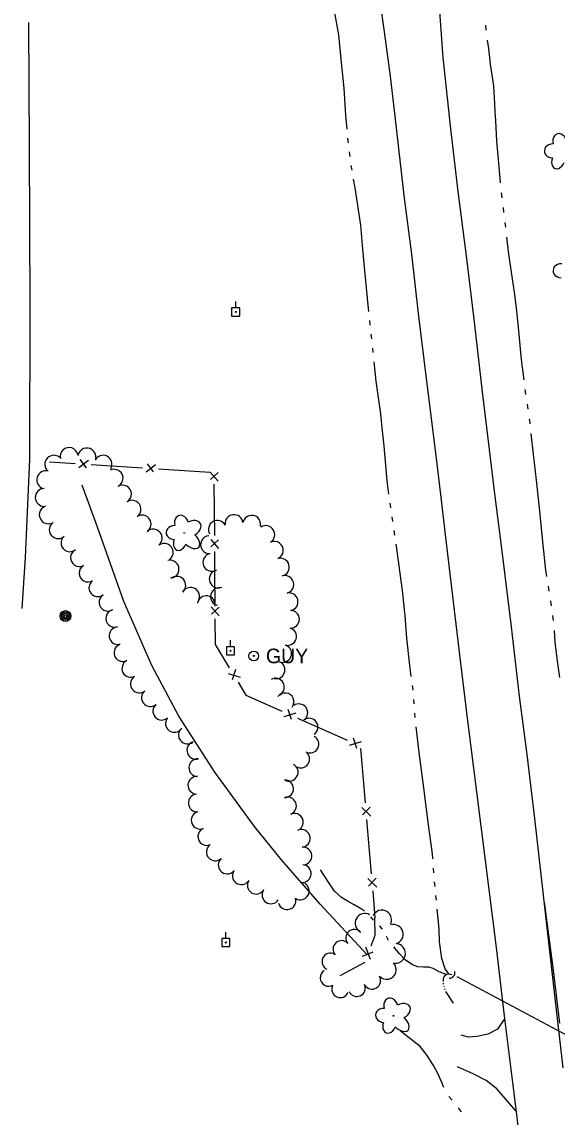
# Model space of a CAD drawing. Extents: x 589250 to 1188077, y 162953 to 363065.
# Drawn here: x 594851.6 to 595071.9, y 175168.1 to 175619.1 of the extents above; entities that cross this region are included whole.
import ezdxf

# ---------------------------------------------------------------- set-up
doc = ezdxf.new("R2010")
doc.units = 0
for name, color, linetype in [('E_DRN', 7, 'Continuous'), ('E_DRN_Pipe', 7, 'Continuous'), ('E_DWY', 7, 'Continuous'), ('E_FEN_P', 7, 'Continuous'), ('E_LAND_TreeLine_P', 7, 'Continuous'), ('E_LAND_Vegetation', 7, 'Continuous'), ('E_MISCPROP', 7, 'Continuous'), ('E_RDWY', 7, 'Continuous'), ('E_RDWY_Gravel', 7, 'Continuous'), ('E_RR_Abandoned', 7, 'Continuous'), ('E_UTL_EGuyWire', 7, 'Continuous'), ('E_UTL_EPowerPole', 7, 'Continuous'), ('E_WTR_FlowLine', 7, 'Continuous')]:
    doc.layers.add(name, color=color, linetype=linetype)

msp = doc.modelspace()

# ---------------------------------------------------------------- linework, layer by layer
at = {"layer": 'E_DRN'}
msp.add_arc((595027.62, 175227.53), 2.22, 266.2846, 12.5448, dxfattribs=at)
at = {"layer": 'E_DRN_Pipe'}
msp.add_line((595030.57, 175226.03), (595097.49, 175190.31), dxfattribs=at)
at = {"layer": 'E_DWY'}
for p, q in [((594854.29, 175618.91), (594854.66, 175567.59)), ((594854.66, 175567.59), (594854.86, 175502.45)), ((594854.86, 175502.45), (594854.81, 175439.04)), ((594854.81, 175439.04), (594852.91, 175398.48)), ((594852.91, 175398.48), (594851.63, 175377.48)), ((595050.22, 175208.51), (595047.37, 175204.33)), ((595047.37, 175204.33), (595043.36, 175202.25)), ((595035.42, 175201.05), (595032.45, 175201.82)), ((595038.93, 175201.24), (595035.42, 175201.05)), ((595043.36, 175202.25), (595038.93, 175201.24)), ((595037.67, 175185.72), (595030.89, 175188.85)), ((595042.69, 175183.23), (595037.67, 175185.72)), ((595047.06, 175179.79), (595042.69, 175183.23)), ((595055.01, 175170.56), (595047.06, 175179.79))]:
    msp.add_line(p, q, dxfattribs=at)
at = {"layer": 'E_FEN_P'}
for p, q in [((594863, 175437.91), (594873.57, 175437.24)), ((594875.1, 175435.65), (594878.99, 175438.62)), ((594875.47, 175438.85), (594878.04, 175435.53)), ((594880.11, 175436.82), (594890.68, 175436.14)), ((594890.68, 175436.14), (594901.24, 175435.46)), ((594902.77, 175433.88), (594906.66, 175436.85)), ((594903.15, 175437.07), (594905.71, 175433.75)), ((594907.78, 175435.04), (594918.35, 175434.36)), ((594918.35, 175434.36), (594928.91, 175433.69)), ((594929.14, 175433.65), (594932.38, 175429.99)), ((594932.36, 175433.51), (594929.23, 175430.71)), ((594930.66, 175428.74), (594930.74, 175418.15)), ((594930.74, 175418.15), (594930.82, 175407.56)), ((594929.35, 175405.92), (594932.59, 175402.26)), ((594932.56, 175405.78), (594929.44, 175402.98)), ((594930.87, 175401.01), (594930.95, 175390.42)), ((594930.95, 175390.42), (594931.03, 175379.83)), ((594929.55, 175378.19), (594932.79, 175374.53)), ((594932.77, 175378.05), (594929.64, 175375.25)), ((594931.07, 175373.28), (594931.15, 175362.69)), ((594931.15, 175362.69), (594936.97, 175353.09)), ((594939.53, 175352.41), (594938.2, 175348.16)), ((594936.52, 175350.8), (594941.46, 175349.22)), ((594940.58, 175347.15), (594943.8, 175341.83)), ((594943.8, 175341.83), (594948.38, 175339.8)), ((594948.38, 175339.8), (594958.65, 175335.25)), ((594959.59, 175333.11), (594964.55, 175334.64)), ((594961.13, 175336.15), (594962.47, 175331.91)), ((594965, 175332.43), (594975.27, 175327.89)), ((594975.27, 175327.89), (594985.54, 175323.34)), ((594986.48, 175321.2), (594991.44, 175322.73)), ((594988.02, 175324.24), (594989.36, 175320)), ((594991.01, 175319.9), (594991.96, 175308.71)), ((594991.96, 175308.71), (594992.91, 175297.52)), ((594991.49, 175295.66), (594995.21, 175292.05)), ((594994.9, 175295.77), (594991.82, 175292.56)), ((594993.5, 175290.59), (594994.45, 175279.4)), ((594994.45, 175279.4), (594995.39, 175268.21)), ((594993.97, 175266.36), (594997.7, 175262.75)), ((594997.38, 175266.47), (594994.31, 175263.25)), ((594995.98, 175261.29), (594996.93, 175250.1)), ((594997.02, 175243.01), (594996.93, 175250.1)), ((594995.41, 175238.69), (594997.02, 175243.01)), ((594991.79, 175234.42), (594996.12, 175236.09)), ((594995.06, 175233.01), (594993.15, 175238.07)), ((594982.57, 175226.36), (594992.87, 175231.91))]:
    msp.add_line(p, q, dxfattribs=at)
at = {"layer": 'E_LAND_TreeLine_P'}
for centre, radius, start, end in [((594871.06, 175440.13), 3.69, 13.4909, 193.4909), ((594878.33, 175439.96), 3.69, 352.1858, 172.1858), ((594864.73, 175436.96), 3.69, 47.686, 227.686), ((594885.01, 175436.94), 3.69, 332.6967, 152.6967), ((594861.45, 175430.55), 3.69, 73.4843, 253.4843), ((594889.56, 175431.18), 3.69, 296.8918, 116.8918), ((594860.83, 175423.26), 3.69, 90.8383, 270.8383), ((594892.99, 175424.64), 3.69, 301.6011, 121.6011), ((594862.46, 175416.13), 3.69, 107.9411, 287.9411), ((594896.94, 175418.41), 3.69, 304.5284, 124.5284), ((594901.1, 175412.31), 3.69, 303.5736, 123.5736), ((594938.91, 175412.48), 3.69, 7.2972, 187.2972), ((594946.19, 175412.21), 3.69, 347.9633, 167.9633), ((594866.58, 175410.02), 3.69, 124.7129, 304.7129), ((594932.07, 175410.09), 3.69, 29.4488, 209.4488), ((594951.97, 175407.97), 3.69, 302.2679, 122.2679), ((594871.37, 175404.54), 3.64, 130.361, 310.361), ((594905.64, 175406.5), 3.69, 310.1278, 130.1278), ((594928.84, 175403.82), 3.69, 94.1402, 274.1402), ((594875.27, 175398.46), 3.64, 116.1845, 296.1845), ((594910.16, 175400.66), 3.69, 306.376, 126.376), ((594955.51, 175401.51), 3.69, 293.8896, 113.8896), ((594912.59, 175393.75), 3.69, 284.5453, 104.5453), ((594929.8, 175396.56), 3.69, 112.8295, 292.8295), ((594957.97, 175394.57), 3.69, 284.8746, 104.8746), ((594878.83, 175392.11), 3.64, 121.0948, 301.0948), ((594932.41, 175389.68), 3.69, 99.9286, 279.9286), ((594882.86, 175386.07), 3.64, 127.4454, 307.4454), ((594915.35, 175387.09), 3.69, 312.147, 132.147), ((594959.83, 175387.43), 3.69, 284.4572, 104.4572), ((594921.03, 175382.54), 3.69, 330.9068, 150.9068), ((594932.95, 175382.43), 3.69, 75.7699, 255.7699), ((594961.61, 175380.32), 3.64, 283.6426, 103.6426), ((594887.03, 175380.11), 3.64, 123.3095, 303.3095), ((594927.48, 175379.09), 3.69, 350.054, 170.054), ((594889.83, 175373.46), 3.64, 107.0985, 287.0985), ((594962.17, 175373.11), 3.64, 269.8673, 89.8673), ((594891.19, 175366.33), 3.64, 98.3622, 278.3622), ((594961, 175366), 3.64, 253.6859, 73.6859), ((594893.19, 175359.36), 3.64, 108.8726, 288.8726), ((594958.95, 175359.01), 3.64, 248.1445, 68.1445), ((594896.44, 175352.85), 3.64, 117.4034, 297.4034), ((594956.24, 175352.26), 3.64, 248.1445, 68.1445), ((594899.92, 175346.48), 3.64, 129.2249, 309.2249), ((594955.99, 175345.18), 3.64, 299.7893, 119.7893), ((594904.53, 175340.84), 3.64, 129.2249, 309.2249), ((594959.92, 175339.13), 3.64, 322.9634, 142.9634), ((594965.59, 175334.62), 3.64, 305.5335, 125.5335), ((594909.18, 175335.25), 3.64, 131.0747, 311.0747), ((594914.35, 175330.19), 3.64, 144.4075, 324.4075), ((594969.82, 175328.7), 3.64, 305.5335, 125.5335), ((594919.74, 175325.4), 3.64, 128.4069, 308.4069), ((594970.22, 175321.67), 3.64, 242.1324, 62.1324), ((594923.19, 175319.12), 3.64, 107.7659, 287.7659), ((594966.39, 175315.55), 3.64, 225.0943, 45.0943), ((594924.01, 175311.99), 3.64, 88.3488, 268.3488), ((594961.64, 175310.1), 3.64, 241.2605, 61.2605), ((594923.61, 175304.73), 3.64, 86.3006, 266.3006), ((594959.77, 175303.32), 3.64, 270.8383, 90.8383), ((594923.76, 175297.47), 3.64, 95.0437, 275.0437), ((594960.94, 175296.25), 3.64, 291.5128, 111.5128), ((594924.98, 175290.36), 3.64, 111.2879, 291.2879), ((594963.73, 175289.53), 3.64, 294.4677, 114.4677), ((594927.69, 175283.6), 3.64, 115.8552, 295.8552), ((594966.58, 175282.86), 3.64, 275.6823, 95.6823), ((594931.21, 175277.29), 3.64, 132.1069, 312.1069), ((594967.3, 175275.62), 3.64, 275.6823, 95.6823), ((594936.09, 175271.89), 3.64, 132.1069, 312.1069), ((594967.03, 175268.35), 3.64, 267.6585, 87.6585), ((594941.91, 175267.51), 3.64, 143.0444, 323.0444), ((594948.04, 175263.59), 3.64, 148.1578, 328.1578), ((594954.1, 175259.57), 3.64, 145.6719, 325.6719), ((594966.2, 175261.22), 3.64, 239.5746, 59.5746), ((594960.77, 175257.18), 3.64, 196.547, 16.547), ((594999.74, 175249.35), 4, 334.2733, 154.2733), ((594992.75, 175247.95), 4, 60.8794, 240.8794), ((594988.43, 175241.88), 3.5, 40.7462, 220.7462), ((595004.54, 175243.39), 4, 285.1877, 105.1877), ((594983.17, 175237.28), 3.5, 41.602, 221.602), ((595005.43, 175235.5), 4, 256.8021, 76.8021), ((594978.64, 175232.1), 3.5, 63.7428, 243.7428), ((595001.67, 175228.83), 4, 222.9809, 42.9809), ((594977.86, 175225.45), 3.5, 121.3681, 301.3681), ((594995.74, 175224.31), 3.5, 211.6011, 31.6011), ((594982.62, 175220.79), 3.5, 157.209, 337.209), ((594989.45, 175221.27), 3.5, 204.1561, 24.1561)]:
    msp.add_arc(centre, radius, start, end, dxfattribs=at)
at = {"layer": 'E_LAND_Vegetation'}
for centre in [(594918.41, 175408.63), (595004.56, 175209.79)]:
    msp.add_circle(centre, 0.128, dxfattribs=at)
for centre, major_axis, ratio in [((595072.95, 175569.54), (0.89, -3.5), 0.782863), ((595070.08, 175565.98), (3.45, -0.15), 0.832022), ((595072.37, 175562.16), (1.33, 3.37), 0.716896), ((595073.64, 175516.62), (3.45, -0.15), 0.832022), ((594917.3, 175412.38), (0.89, -3.5), 0.782863), ((594914.43, 175408.81), (3.45, -0.15), 0.832022), ((594921.41, 175410.49), (-3.73, -1.98), 0.691916), ((594916.73, 175404.99), (1.33, 3.37), 0.716896), ((594920.97, 175405.99), (-3.45, 3.27), 0.560249), ((595003.45, 175213.54), (0.89, -3.5), 0.782863), ((595000.58, 175209.97), (3.45, -0.15), 0.832022), ((595007.56, 175211.65), (-3.73, -1.98), 0.691916), ((595007.11, 175207.15), (-3.45, 3.27), 0.560249), ((595002.87, 175206.15), (1.33, 3.37), 0.716896)]:
    msp.add_ellipse(centre, major_axis=major_axis, ratio=ratio, start_param=1.570796, end_param=4.712389, dxfattribs=at)
at = {"layer": 'E_MISCPROP'}
for radius in [2.23, 1.67, 1.12, 0.558]:
    msp.add_circle((594869.56, 175374.43), radius, dxfattribs=at)
at = {"layer": 'E_RDWY'}
for p, q in [((594998.92, 175627.62), (595000.77, 175615.04)), ((595025, 175604.5), (595022.98, 175631.33)), ((595000.77, 175615.04), (595003.15, 175596.7)), ((595028.15, 175575.06), (595025, 175604.5)), ((595003.15, 175596.7), (595005.67, 175575.46)), ((595005.67, 175575.46), (595008.87, 175547.58)), ((595031.12, 175549.29), (595028.15, 175575.06)), ((595008.87, 175547.58), (595011.91, 175523.51)), ((595034.68, 175521.63), (595031.12, 175549.29)), ((595011.91, 175523.51), (595014.67, 175499.07)), ((595037.99, 175494.29), (595034.68, 175521.63)), ((595014.67, 175499.07), (595018.09, 175471.14)), ((595041.21, 175466.8), (595037.99, 175494.29)), ((595018.09, 175471.14), (595021.71, 175442.71)), ((595044.08, 175442.99), (595041.21, 175466.8)), ((595021.71, 175442.71), (595023.89, 175424.5)), ((595046.17, 175425.82), (595044.08, 175442.99)), ((595023.89, 175424.5), (595025.76, 175408)), ((595049.07, 175402.23), (595046.17, 175425.82)), ((595025.76, 175408), (595029.1, 175380.34)), ((595053.06, 175370.04), (595049.07, 175402.23)), ((595029.1, 175380.34), (595032.19, 175355.08)), ((595056.36, 175341.48), (595053.06, 175370.04)), ((595032.19, 175355.08), (595034.96, 175331.3)), ((595059.6, 175317.41), (595056.36, 175341.48)), ((595034.96, 175331.3), (595038.71, 175302.09)), ((595062.73, 175291.06), (595059.6, 175317.41)), ((595038.71, 175302.09), (595042.28, 175273.75)), ((595067.82, 175246.23), (595062.73, 175291.06)), ((595042.28, 175273.75), (595046.76, 175237.94)), ((595071.11, 175217.11), (595067.82, 175246.23)), ((595046.76, 175237.94), (595050.06, 175209.74)), ((595074.43, 175188.42), (595071.11, 175217.11)), ((595050.06, 175209.74), (595054.09, 175177.94)), ((595054.09, 175177.94), (595057.67, 175149.2))]:
    msp.add_line(p, q, dxfattribs=at)
at = {"layer": 'E_RDWY_Gravel'}
for p, q in [((595070.31, 175229.75), (595066.65, 175256.59)), ((595073.04, 175206.84), (595070.31, 175229.75))]:
    msp.add_line(p, q, dxfattribs=at)
at = {"layer": 'E_RR_Abandoned'}
for p, q in [((594882.7, 175411.03), (594876.38, 175428.31)), ((594893.58, 175380.42), (594882.7, 175411.03)), ((594905.11, 175354.1), (594893.58, 175380.42)), ((594916.22, 175333.18), (594905.11, 175354.1)), ((594931.06, 175310.1), (594916.22, 175333.18)), ((594947.36, 175287.7), (594931.06, 175310.1)), ((594958.43, 175274.08), (594947.36, 175287.7)), ((594974.41, 175255.75), (594958.43, 175274.08)), ((594993.76, 175234.88), (594974.41, 175255.75))]:
    msp.add_line(p, q, dxfattribs=at)
at = {"layer": 'E_UTL_EGuyWire'}
for radius in [2, 0.25]:
    msp.add_circle((594947.06, 175358), radius, dxfattribs=at)
at = {"layer": 'E_UTL_EPowerPole'}
for points in [[(594941.29, 175501.34), (594937.94, 175501.34)], [(594937.94, 175501.34), (594937.94, 175497.99)], [(594939.61, 175501.34), (594939.61, 175503.99)], [(594941.29, 175497.99), (594941.29, 175501.34)], [(594937.94, 175497.99), (594941.29, 175497.99)], [(594939.12, 175361.8), (594935.76, 175361.8)], [(594935.76, 175361.8), (594935.76, 175358.45)], [(594937.44, 175361.8), (594937.44, 175364.45)], [(594939.12, 175358.45), (594939.12, 175361.8)], [(594935.76, 175358.45), (594939.12, 175358.45)], [(594935.56, 175241.67), (594935.56, 175244.32)], [(594937.24, 175241.67), (594933.89, 175241.67)], [(594933.89, 175241.67), (594933.89, 175238.32)], [(594937.24, 175238.32), (594937.24, 175241.67)], [(594933.89, 175238.32), (594937.24, 175238.32)]]:
    msp.add_lwpolyline(points, dxfattribs=at)
for centre in [(594939.64, 175499.67), (594937.47, 175360.13), (594935.59, 175240)]:
    msp.add_circle(centre, 0.217, dxfattribs=at)
at = {"layer": 'E_WTR_FlowLine'}
for p, q in [((594982.1, 175613.82), (594980.46, 175622.77)), ((594983.03, 175603.7), (594982.1, 175613.82)), ((595042.47, 175617.7), (595042.61, 175615.67)), ((595043.09, 175611.62), (595043.65, 175608.2)), ((595043.65, 175608.2), (595044.34, 175601.67)), ((594983.17, 175602.32), (594983.03, 175603.7)), ((594984.28, 175591.81), (594983.17, 175602.32)), ((595044.34, 175601.67), (595045.64, 175592.82)), ((594984.92, 175580.61), (594984.28, 175591.81)), ((595045.64, 175592.82), (595046.12, 175585.33)), ((595046.12, 175585.33), (595046.32, 175582.25)), ((595046.32, 175582.25), (595046.57, 175578.42)), ((594985.46, 175574.99), (594984.92, 175580.61)), ((595046.57, 175578.42), (595047, 175570.02)), ((594985.94, 175569.97), (594985.82, 175571.22)), ((594986.01, 175569.34), (594985.94, 175569.97)), ((595047, 175570.02), (595047.78, 175560.95)), ((594986.68, 175563.7), (594986.46, 175565.58)), ((594987.48, 175558.09), (594987.15, 175559.95)), ((595047.78, 175560.95), (595048.39, 175553.12)), ((594988.76, 175550.82), (594988.14, 175554.36)), ((594991.06, 175535.41), (594988.76, 175550.82)), ((595048.39, 175553.12), (595048.44, 175552.76)), ((595048.91, 175548.71), (595049.15, 175546.68)), ((595049.63, 175542.63), (595049.87, 175540.61)), ((594991.81, 175527.18), (594991.06, 175535.41)), ((595050.35, 175536.55), (595050.58, 175534.53)), ((595051.04, 175530.48), (595051.84, 175523.47)), ((594992.5, 175519.56), (594991.81, 175527.18)), ((595051.84, 175523.47), (595054.34, 175506.89)), ((594994.13, 175502.5), (594992.5, 175519.56)), ((595054.34, 175506.89), (595054.98, 175501.17)), ((594994.41, 175499.87), (594994.13, 175502.5)), ((595054.98, 175501.17), (595055.84, 175493.39)), ((594995.01, 175494.22), (594994.81, 175496.1)), ((595055.84, 175493.39), (595057.12, 175480.08)), ((594995.62, 175488.58), (594995.42, 175490.46)), ((594996.22, 175482.93), (594996.02, 175484.81)), ((594997.43, 175471.19), (594996.61, 175479.17)), ((595057.12, 175480.08), (595058.16, 175471.77)), ((594999.27, 175457.67), (594997.43, 175471.19)), ((595058.66, 175467.72), (595058.77, 175466.86)), ((595058.77, 175466.86), (595058.94, 175465.7)), ((595059.53, 175461.67), (595059.82, 175459.65)), ((594999.88, 175451.93), (594999.27, 175457.67)), ((595060.41, 175455.61), (595060.46, 175455.29)), ((595000.67, 175444.58), (594999.88, 175451.93)), ((595060.46, 175455.29), (595060.66, 175453.59)), ((595061.12, 175449.54), (595062.09, 175441.09)), ((595001.96, 175430.15), (595000.67, 175444.58)), ((595062.09, 175441.09), (595063.24, 175430.38)), ((595002.68, 175424.64), (595001.96, 175430.15)), ((595063.24, 175430.38), (595064.41, 175420.15)), ((595003.42, 175419.01), (595003.17, 175420.89)), ((595064.41, 175420.15), (595064.52, 175419.14)), ((595004.22, 175413.39), (595003.94, 175415.26)), ((595064.52, 175419.14), (595065.8, 175406.33)), ((595005.05, 175407.77), (595004.77, 175409.65)), ((595065.8, 175406.33), (595067.13, 175393.32)), ((595005.86, 175402.25), (595005.6, 175404.03)), ((595008.42, 175383.79), (595005.86, 175402.25)), ((595067.13, 175393.32), (595067.54, 175390.75)), ((595009.08, 175376.82), (595008.42, 175383.79)), ((595068.19, 175386.72), (595068.51, 175384.71)), ((595069.15, 175380.68), (595069.32, 175379.62)), ((595069.32, 175379.62), (595069.44, 175378.66)), ((595009.29, 175374.61), (595009.08, 175376.82)), ((595009.98, 175365.26), (595009.29, 175374.61)), ((595069.95, 175374.61), (595070.21, 175372.59)), ((595070.62, 175368.53), (595071.01, 175363.71)), ((595011.08, 175355.31), (595009.98, 175365.26)), ((595071.01, 175363.71), (595071.79, 175357)), ((595071.79, 175357), (595072.93, 175349.08)), ((595011.88, 175349.53), (595011.08, 175355.31)), ((595012.48, 175345.2), (595012.4, 175345.79)), ((595012.58, 175343.9), (595012.48, 175345.2)), ((595013.04, 175338.25), (595012.89, 175340.13)), ((595013.48, 175332.79), (595013.34, 175334.47)), ((595013.5, 175332.59), (595013.48, 175332.79)), ((595015.07, 175318.19), (595013.91, 175328.83)), ((595017.27, 175301.6), (595015.07, 175318.19)), ((595017.3, 175301.4), (595017.27, 175301.6)), ((595018.91, 175288.44), (595017.3, 175301.4)), ((595020.6, 175276.56), (595018.91, 175288.44)), ((595020.76, 175274.39), (595020.6, 175276.56)), ((595021.18, 175268.73), (595021.04, 175270.62)), ((594977.84, 175264.86), (594974.5, 175269.9)), ((594980.32, 175261.19), (594977.84, 175264.86)), ((595021.65, 175263.07), (595021.46, 175264.96)), ((594983.16, 175258.5), (594980.32, 175261.19)), ((594985.88, 175256.82), (594983.16, 175258.5)), ((595022.2, 175257.42), (595022.02, 175259.31)), ((594988.43, 175255.48), (594985.88, 175256.82)), ((594990.98, 175254.03), (594988.43, 175255.48)), ((594992.56, 175252.87), (594990.98, 175254.03)), ((595023.34, 175245.59), (595022.57, 175253.66)), ((594996.34, 175249.25), (594995.2, 175250.58)), ((594999.11, 175246.57), (594998.84, 175246.81)), ((594999.98, 175245.48), (594999.11, 175246.57)), ((595023.54, 175240.29), (595023.34, 175245.59)), ((595002.43, 175240.88), (595001.72, 175242.48)), ((595024.38, 175233.44), (595023.54, 175240.29)), ((595007.05, 175235.4), (595004.64, 175238.17)), ((595009.32, 175232.87), (595007.05, 175235.4)), ((595012.38, 175230.79), (595009.32, 175232.87)), ((595014.55, 175230.01), (595012.38, 175230.79)), ((595016.94, 175229.78), (595014.55, 175230.01)), ((595025.86, 175229.15), (595024.38, 175233.44)), ((595019.07, 175229.78), (595016.94, 175229.78)), ((595020.86, 175229.33), (595019.07, 175229.78)), ((595023.3, 175227.98), (595020.86, 175229.33)), ((595026.16, 175226.8), (595023.3, 175227.98)), ((595025.15, 175225.21), (595025.52, 175226.34)), ((595025.52, 175226.34), (595026.33, 175226.91)), ((595027.34, 175227.04), (595025.86, 175229.15)), ((595026.33, 175226.91), (595027.23, 175227.05)), ((595027.23, 175227.05), (595028.62, 175226.86)), ((595025.19, 175222.84), (595025.09, 175223.22)), ((595025.11, 175224), (595025.15, 175225.21)), ((595025.47, 175221.69), (595025.38, 175222.07)), ((595025.76, 175220.55), (595025.67, 175220.93)), ((595029.18, 175215.05), (595026.06, 175219.83)), ((595015.46, 175197.21), (595007.35, 175203.6)), ((595018.36, 175193.41), (595015.46, 175197.21)), ((595020.97, 175189.31), (595018.36, 175193.41)), ((595022.74, 175186.05), (595020.97, 175189.31)), ((595024.48, 175182.37), (595022.74, 175186.05)), ((595025.26, 175180.23), (595024.48, 175182.37)), ((595028.63, 175175.07), (595027.27, 175176.63)), ((595032.51, 175170.23), (595031.25, 175171.87))]:
    msp.add_line(p, q, dxfattribs=at)

# ---------------------------------------------------------------- texts
at = {"layer": 'E_UTL_EGuyWire'}
msp.add_text('GUY', height=6, dxfattribs=at).set_placement((594952.06, 175355))

doc.saveas('drawing.dxf')
